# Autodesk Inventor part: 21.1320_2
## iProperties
Created: 2006-12
Part Number: 21.1320_2
Document SubType Name: Modeling
Designer: Andy Moles
Material: Steel, Mild
Density: 7.86 g/cm^3
Mass: 5.5784 g
Surface Area: 8.43697 cm^2
Volume: 0.70972 cm^3
Author: Andy Moles
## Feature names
1. Extrusion1
2. Revolution1
3. Extrusion3
4. Fillet2
5. Fillet3
